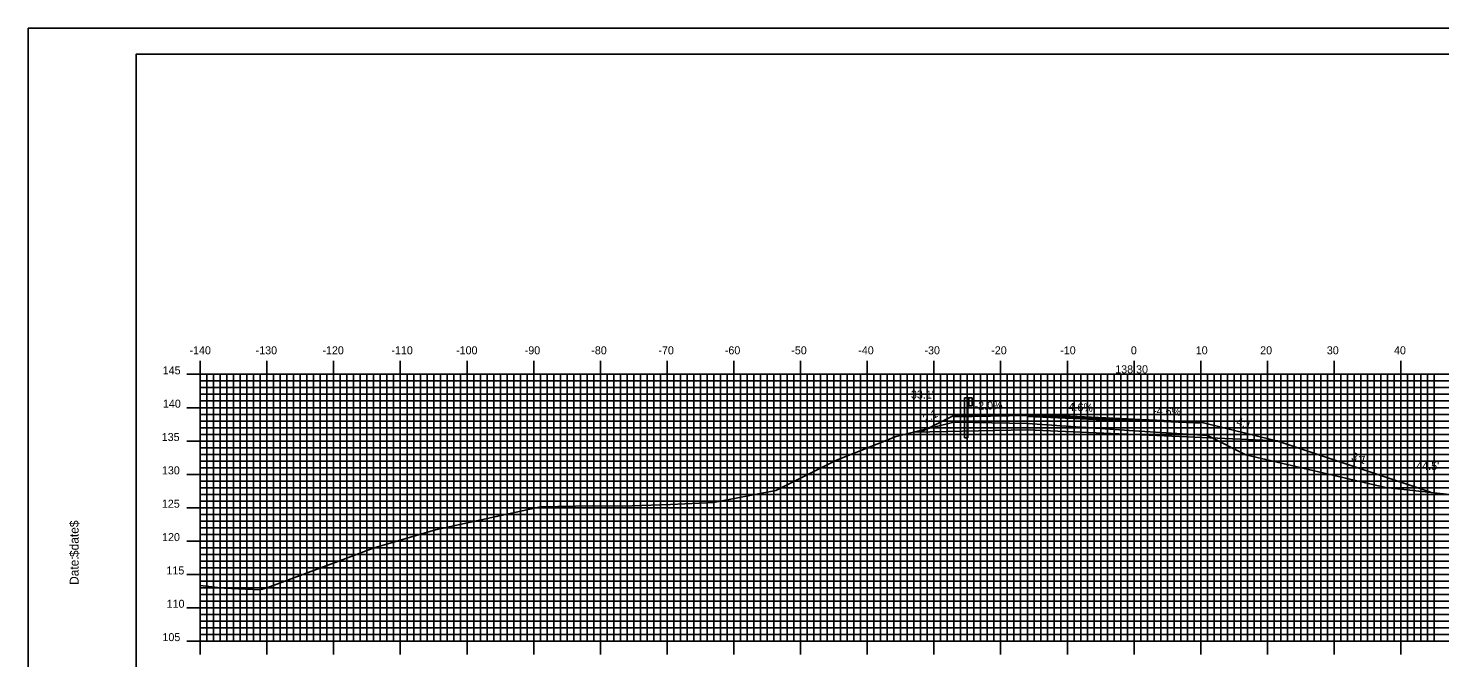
# Model space of a CAD drawing. Extents: x 851753 to 852097, y 364661 to 364881.
# Drawn here: x 851753.5 to 851965.1, y 364786.9 to 364881.3 of the extents above; entities that cross this region are included whole.
import ezdxf

# ---------------------------------------------------------------- set-up
doc = ezdxf.new("R2010")
doc.units = 0
for name, color, linetype in [('ANNOTATION', 7, 'Continuous'), ('BORDER', 7, 'Continuous'), ('D_Guardrail_Beam_Lt', 7, 'Continuous'), ('D_Roadway_Centerline_Text', 7, 'Continuous'), ('D_Roadway_Edge_Shoulder', 7, 'Continuous'), ('D_Roadway_Edge_TW', 7, 'Continuous'), ('D_Roadway_Pavement', 7, 'Continuous'), ('D_Roadway_SlopeLines', 7, 'Continuous'), ('D_Roadway_SubGrade', 7, 'Continuous'), ('D_Text_Standard', 7, 'Continuous'), ('H_V ANNOTATION', 7, 'Continuous'), ('M_Roadway_Centerline', 7, 'Continuous'), ('MAJOR', 7, 'Continuous'), ('MINOR', 7, 'Continuous'), ('PLOT BOUNDARY', 7, 'Continuous'), ('S_Roadway_Centerline', 7, 'Continuous')]:
    doc.layers.add(name, color=color, linetype=linetype)

msp = doc.modelspace()

# ---------------------------------------------------------------- linework, layer by layer
at = {"layer": 'BORDER'}
msp.add_lwpolyline([(851769.64, 364667.37), (852089.64, 364667.37), (852089.64, 364877.37), (851769.64, 364877.37)], close=True, dxfattribs=at)
at = {"layer": 'D_Guardrail_Beam_Lt'}
for p, q in [((851893.81, 364825.83), (851893.81, 364819.83)), ((851894.28, 364825.83), (851893.81, 364825.83)), ((851894.97, 364825.83), (851894.28, 364825.83)), ((851894.28, 364825.83), (851894.28, 364824.66)), ((851894.28, 364824.66), (851894.97, 364824.66)), ((851894.3, 364819.83), (851894.3, 364824.66)), ((851894.35, 364825.83), (851894.35, 364824.66)), ((851894.45, 364825.83), (851894.45, 364824.66)), ((851894.97, 364824.66), (851894.97, 364825.83)), ((851894.97, 364825.74), (851895.05, 364825.73)), ((851895.05, 364824.76), (851894.97, 364824.74)), ((851894.98, 364825.28), (851894.98, 364825.21)), ((851895.2, 364825.48), (851895.01, 364825.34)), ((851895.01, 364825.14), (851895.2, 364825.01)), ((851895.06, 364825.72), (851895.2, 364825.62)), ((851895.2, 364824.86), (851895.06, 364824.76)), ((851894.3, 364819.83), (851893.81, 364819.83))]:
    msp.add_line(p, q, dxfattribs=at)
for centre, major_axis, start_param, end_param in [((851895.05, 364825.28), (-0.0789, 0), 5.323254, 6.283185), ((851895.05, 364825.21), (-0.0789, 0), 6.283185, 7.243116), ((851895.04, 364825.69), (0.0417, 0), 0.959931, 1.376053), ((851895.04, 364824.8), (0.0417, 0), 4.907132, 5.323254), ((851895.15, 364825.55), (0.0877, 0), 5.323254, 7.243116), ((851895.15, 364824.94), (0.0877, 0), 5.323254, 7.243116)]:
    msp.add_ellipse(centre, major_axis=major_axis, ratio=0.995501, start_param=start_param, end_param=end_param, dxfattribs=at)
at = {"layer": 'D_Roadway_Edge_Shoulder'}
msp.add_lwpolyline([(851903.24, 364823.4), (851892.24, 364823.18), (851892.24, 364823.02), (851903.24, 364823.21)], close=True, dxfattribs=at)
at = {"layer": 'D_Roadway_Edge_TW'}
msp.add_line((851919.24, 364822.67), (851929.24, 364822.21), dxfattribs=at)
msp.add_lwpolyline([(851903.24, 364823.4), (851919.24, 364822.67), (851919.24, 364822.5), (851903.24, 364823.21)], close=True, dxfattribs=at)
msp.add_lwpolyline([(851919.24, 364822.5), (851929.24, 364822.04), (851929.24, 364822.21)], dxfattribs=at)
at = {"layer": 'D_Roadway_Pavement'}
msp.add_lwpolyline([(851903.24, 364823.21), (851919.24, 364822.5), (851919.24, 364822.33), (851903.24, 364823.05)], close=True, dxfattribs=at)
for points in [[(851903.24, 364823.21), (851903.24, 364823.05)], [(851919.24, 364822.5), (851919.24, 364822.33)], [(851919.24, 364822.5), (851919.24, 364822.33)]]:
    msp.add_lwpolyline(points, dxfattribs=at)
at = {"layer": 'D_Roadway_SlopeLines'}
msp.add_line((851892.24, 364823.18), (851887.33, 364820.73), dxfattribs=at)
msp.add_lwpolyline([(851929.24, 364822.21), (851940.77, 364819.33), (851963.41, 364811.78)], dxfattribs=at)
at = {"layer": 'D_Roadway_SubGrade'}
for p, q in [((851919.24, 364820.33), (851940.77, 364819.39)), ((851963.41, 364811.78), (851963.77, 364811.66))]:
    msp.add_line(p, q, dxfattribs=at)
msp.add_lwpolyline([(851903.24, 364823.05), (851919.24, 364822.33), (851919.24, 364820.33), (851903.24, 364821.05)], close=True, dxfattribs=at)
msp.add_lwpolyline([(851903.24, 364821.98), (851903.24, 364821.05), (851886.18, 364820.7)], dxfattribs=at)
at = {"layer": 'MAJOR'}
for p, q in [((851779.24, 364831.37), (851779.24, 364829.37)), ((851789.24, 364831.37), (851789.24, 364829.37)), ((851799.24, 364831.37), (851799.24, 364829.37)), ((851809.24, 364831.37), (851809.24, 364829.37)), ((851819.24, 364831.37), (851819.24, 364829.37)), ((851829.24, 364831.37), (851829.24, 364829.37)), ((851839.24, 364831.37), (851839.24, 364829.37)), ((851849.24, 364831.37), (851849.24, 364829.37)), ((851859.24, 364831.37), (851859.24, 364829.37)), ((851869.24, 364831.37), (851869.24, 364829.37)), ((851879.24, 364831.37), (851879.24, 364829.37)), ((851889.24, 364831.37), (851889.24, 364829.37)), ((851899.24, 364831.37), (851899.24, 364829.37)), ((851909.24, 364831.37), (851909.24, 364829.37)), ((851919.24, 364831.37), (851919.24, 364829.37)), ((851929.24, 364831.37), (851929.24, 364829.37)), ((851939.24, 364831.37), (851939.24, 364829.37)), ((851949.24, 364831.37), (851949.24, 364829.37)), ((851959.24, 364831.37), (851959.24, 364829.37)), ((851777.24, 364829.37), (851779.24, 364829.37)), ((851779.24, 364829.37), (852059.24, 364829.37)), ((851779.24, 364789.37), (851779.24, 364829.37)), ((851779.24, 364789.37), (851779.24, 364829.37)), ((851779.24, 364829.37), (852059.24, 364829.37)), ((851789.24, 364789.37), (851789.24, 364829.37)), ((851799.24, 364789.37), (851799.24, 364829.37)), ((851809.24, 364789.37), (851809.24, 364829.37)), ((851819.24, 364789.37), (851819.24, 364829.37)), ((851829.24, 364789.37), (851829.24, 364829.37)), ((851839.24, 364789.37), (851839.24, 364829.37)), ((851849.24, 364789.37), (851849.24, 364829.37)), ((851859.24, 364789.37), (851859.24, 364829.37)), ((851869.24, 364789.37), (851869.24, 364829.37)), ((851879.24, 364789.37), (851879.24, 364829.37)), ((851889.24, 364789.37), (851889.24, 364829.37)), ((851899.24, 364789.37), (851899.24, 364829.37)), ((851909.24, 364789.37), (851909.24, 364829.37)), ((851919.24, 364789.37), (851919.24, 364829.37)), ((851929.24, 364789.37), (851929.24, 364829.37)), ((851939.24, 364789.37), (851939.24, 364829.37)), ((851949.24, 364789.37), (851949.24, 364829.37)), ((851959.24, 364789.37), (851959.24, 364829.37)), ((851777.24, 364824.37), (851779.24, 364824.37)), ((851779.24, 364824.37), (852059.24, 364824.37)), ((851777.24, 364819.37), (851779.24, 364819.37)), ((851779.24, 364819.37), (852059.24, 364819.37)), ((851777.24, 364814.37), (851779.24, 364814.37)), ((851779.24, 364814.37), (852059.24, 364814.37)), ((851777.24, 364809.37), (851779.24, 364809.37)), ((851779.24, 364809.37), (852059.24, 364809.37)), ((851777.24, 364804.37), (851779.24, 364804.37)), ((851779.24, 364804.37), (852059.24, 364804.37)), ((851777.24, 364799.37), (851779.24, 364799.37)), ((851779.24, 364799.37), (852059.24, 364799.37)), ((851777.24, 364794.37), (851779.24, 364794.37)), ((851779.24, 364794.37), (852059.24, 364794.37)), ((851777.24, 364789.37), (851779.24, 364789.37)), ((851779.24, 364789.37), (852059.24, 364789.37)), ((851779.24, 364789.37), (852059.24, 364789.37)), ((851779.24, 364787.37), (851779.24, 364789.37)), ((851789.24, 364787.37), (851789.24, 364789.37)), ((851799.24, 364787.37), (851799.24, 364789.37)), ((851809.24, 364787.37), (851809.24, 364789.37)), ((851819.24, 364787.37), (851819.24, 364789.37)), ((851829.24, 364787.37), (851829.24, 364789.37)), ((851839.24, 364787.37), (851839.24, 364789.37)), ((851849.24, 364787.37), (851849.24, 364789.37)), ((851859.24, 364787.37), (851859.24, 364789.37)), ((851869.24, 364787.37), (851869.24, 364789.37)), ((851879.24, 364787.37), (851879.24, 364789.37)), ((851889.24, 364787.37), (851889.24, 364789.37)), ((851899.24, 364787.37), (851899.24, 364789.37)), ((851909.24, 364787.37), (851909.24, 364789.37)), ((851919.24, 364787.37), (851919.24, 364789.37)), ((851929.24, 364787.37), (851929.24, 364789.37)), ((851939.24, 364787.37), (851939.24, 364789.37)), ((851949.24, 364787.37), (851949.24, 364789.37)), ((851959.24, 364787.37), (851959.24, 364789.37))]:
    msp.add_line(p, q, dxfattribs=at)
at = {"layer": 'MINOR'}
for p, q in [((851780.24, 364789.37), (851780.24, 364829.37)), ((851781.24, 364789.37), (851781.24, 364829.37)), ((851782.24, 364789.37), (851782.24, 364829.37)), ((851783.24, 364789.37), (851783.24, 364829.37)), ((851784.24, 364789.37), (851784.24, 364829.37)), ((851785.24, 364789.37), (851785.24, 364829.37)), ((851786.24, 364789.37), (851786.24, 364829.37)), ((851787.24, 364789.37), (851787.24, 364829.37)), ((851788.24, 364789.37), (851788.24, 364829.37)), ((851790.24, 364789.37), (851790.24, 364829.37)), ((851791.24, 364789.37), (851791.24, 364829.37)), ((851792.24, 364789.37), (851792.24, 364829.37)), ((851793.24, 364789.37), (851793.24, 364829.37)), ((851794.24, 364789.37), (851794.24, 364829.37)), ((851795.24, 364789.37), (851795.24, 364829.37)), ((851796.24, 364789.37), (851796.24, 364829.37)), ((851797.24, 364789.37), (851797.24, 364829.37)), ((851798.24, 364789.37), (851798.24, 364829.37)), ((851800.24, 364789.37), (851800.24, 364829.37)), ((851801.24, 364789.37), (851801.24, 364829.37)), ((851802.24, 364789.37), (851802.24, 364829.37)), ((851803.24, 364789.37), (851803.24, 364829.37)), ((851804.24, 364789.37), (851804.24, 364829.37)), ((851805.24, 364789.37), (851805.24, 364829.37)), ((851806.24, 364789.37), (851806.24, 364829.37)), ((851807.24, 364789.37), (851807.24, 364829.37)), ((851808.24, 364789.37), (851808.24, 364829.37)), ((851810.24, 364789.37), (851810.24, 364829.37)), ((851811.24, 364789.37), (851811.24, 364829.37)), ((851812.24, 364789.37), (851812.24, 364829.37)), ((851813.24, 364789.37), (851813.24, 364829.37)), ((851814.24, 364789.37), (851814.24, 364829.37)), ((851815.24, 364789.37), (851815.24, 364829.37)), ((851816.24, 364789.37), (851816.24, 364829.37)), ((851817.24, 364789.37), (851817.24, 364829.37)), ((851818.24, 364789.37), (851818.24, 364829.37)), ((851820.24, 364789.37), (851820.24, 364829.37)), ((851821.24, 364789.37), (851821.24, 364829.37)), ((851822.24, 364789.37), (851822.24, 364829.37)), ((851823.24, 364789.37), (851823.24, 364829.37)), ((851824.24, 364789.37), (851824.24, 364829.37)), ((851825.24, 364789.37), (851825.24, 364829.37)), ((851826.24, 364789.37), (851826.24, 364829.37)), ((851827.24, 364789.37), (851827.24, 364829.37)), ((851828.24, 364789.37), (851828.24, 364829.37)), ((851830.24, 364789.37), (851830.24, 364829.37)), ((851831.24, 364789.37), (851831.24, 364829.37)), ((851832.24, 364789.37), (851832.24, 364829.37)), ((851833.24, 364789.37), (851833.24, 364829.37)), ((851834.24, 364789.37), (851834.24, 364829.37)), ((851835.24, 364789.37), (851835.24, 364829.37)), ((851836.24, 364789.37), (851836.24, 364829.37)), ((851837.24, 364789.37), (851837.24, 364829.37)), ((851838.24, 364789.37), (851838.24, 364829.37)), ((851840.24, 364789.37), (851840.24, 364829.37)), ((851841.24, 364789.37), (851841.24, 364829.37)), ((851842.24, 364789.37), (851842.24, 364829.37)), ((851843.24, 364789.37), (851843.24, 364829.37)), ((851844.24, 364789.37), (851844.24, 364829.37)), ((851845.24, 364789.37), (851845.24, 364829.37)), ((851846.24, 364789.37), (851846.24, 364829.37)), ((851847.24, 364789.37), (851847.24, 364829.37)), ((851848.24, 364789.37), (851848.24, 364829.37)), ((851850.24, 364789.37), (851850.24, 364829.37)), ((851851.24, 364789.37), (851851.24, 364829.37)), ((851852.24, 364789.37), (851852.24, 364829.37)), ((851853.24, 364789.37), (851853.24, 364829.37)), ((851854.24, 364789.37), (851854.24, 364829.37)), ((851855.24, 364789.37), (851855.24, 364829.37)), ((851856.24, 364789.37), (851856.24, 364829.37)), ((851857.24, 364789.37), (851857.24, 364829.37)), ((851858.24, 364789.37), (851858.24, 364829.37)), ((851860.24, 364789.37), (851860.24, 364829.37)), ((851861.24, 364789.37), (851861.24, 364829.37)), ((851862.24, 364789.37), (851862.24, 364829.37)), ((851863.24, 364789.37), (851863.24, 364829.37)), ((851864.24, 364789.37), (851864.24, 364829.37)), ((851865.24, 364789.37), (851865.24, 364829.37)), ((851866.24, 364789.37), (851866.24, 364829.37)), ((851867.24, 364789.37), (851867.24, 364829.37)), ((851868.24, 364789.37), (851868.24, 364829.37)), ((851870.24, 364789.37), (851870.24, 364829.37)), ((851871.24, 364789.37), (851871.24, 364829.37)), ((851872.24, 364789.37), (851872.24, 364829.37)), ((851873.24, 364789.37), (851873.24, 364829.37)), ((851874.24, 364789.37), (851874.24, 364829.37)), ((851875.24, 364789.37), (851875.24, 364829.37)), ((851876.24, 364789.37), (851876.24, 364829.37)), ((851877.24, 364789.37), (851877.24, 364829.37)), ((851878.24, 364789.37), (851878.24, 364829.37)), ((851880.24, 364789.37), (851880.24, 364829.37)), ((851881.24, 364789.37), (851881.24, 364829.37)), ((851882.24, 364789.37), (851882.24, 364829.37)), ((851883.24, 364789.37), (851883.24, 364829.37)), ((851884.24, 364789.37), (851884.24, 364829.37)), ((851885.24, 364789.37), (851885.24, 364829.37)), ((851886.24, 364789.37), (851886.24, 364829.37)), ((851887.24, 364789.37), (851887.24, 364829.37)), ((851888.24, 364789.37), (851888.24, 364829.37)), ((851890.24, 364789.37), (851890.24, 364829.37)), ((851891.24, 364789.37), (851891.24, 364829.37)), ((851892.24, 364789.37), (851892.24, 364829.37)), ((851893.24, 364789.37), (851893.24, 364829.37)), ((851894.24, 364789.37), (851894.24, 364829.37)), ((851895.24, 364789.37), (851895.24, 364829.37)), ((851896.24, 364789.37), (851896.24, 364829.37)), ((851897.24, 364789.37), (851897.24, 364829.37)), ((851898.24, 364789.37), (851898.24, 364829.37)), ((851900.24, 364789.37), (851900.24, 364829.37)), ((851901.24, 364789.37), (851901.24, 364829.37)), ((851902.24, 364789.37), (851902.24, 364829.37)), ((851903.24, 364789.37), (851903.24, 364829.37)), ((851904.24, 364789.37), (851904.24, 364829.37)), ((851905.24, 364789.37), (851905.24, 364829.37)), ((851906.24, 364789.37), (851906.24, 364829.37)), ((851907.24, 364789.37), (851907.24, 364829.37)), ((851908.24, 364789.37), (851908.24, 364829.37)), ((851910.24, 364789.37), (851910.24, 364829.37)), ((851911.24, 364789.37), (851911.24, 364829.37)), ((851912.24, 364789.37), (851912.24, 364829.37)), ((851913.24, 364789.37), (851913.24, 364829.37)), ((851914.24, 364789.37), (851914.24, 364829.37)), ((851915.24, 364789.37), (851915.24, 364829.37)), ((851916.24, 364789.37), (851916.24, 364829.37)), ((851917.24, 364789.37), (851917.24, 364829.37)), ((851918.24, 364789.37), (851918.24, 364829.37)), ((851920.24, 364789.37), (851920.24, 364829.37)), ((851921.24, 364789.37), (851921.24, 364829.37)), ((851922.24, 364789.37), (851922.24, 364829.37)), ((851923.24, 364789.37), (851923.24, 364829.37)), ((851924.24, 364789.37), (851924.24, 364829.37)), ((851925.24, 364789.37), (851925.24, 364829.37)), ((851926.24, 364789.37), (851926.24, 364829.37)), ((851927.24, 364789.37), (851927.24, 364829.37)), ((851928.24, 364789.37), (851928.24, 364829.37)), ((851930.24, 364789.37), (851930.24, 364829.37)), ((851931.24, 364789.37), (851931.24, 364829.37)), ((851932.24, 364789.37), (851932.24, 364829.37)), ((851933.24, 364789.37), (851933.24, 364829.37)), ((851934.24, 364789.37), (851934.24, 364829.37)), ((851935.24, 364789.37), (851935.24, 364829.37)), ((851936.24, 364789.37), (851936.24, 364829.37)), ((851937.24, 364789.37), (851937.24, 364829.37)), ((851938.24, 364789.37), (851938.24, 364829.37)), ((851940.24, 364789.37), (851940.24, 364829.37)), ((851941.24, 364789.37), (851941.24, 364829.37)), ((851942.24, 364789.37), (851942.24, 364829.37)), ((851943.24, 364789.37), (851943.24, 364829.37)), ((851944.24, 364789.37), (851944.24, 364829.37)), ((851945.24, 364789.37), (851945.24, 364829.37)), ((851946.24, 364789.37), (851946.24, 364829.37)), ((851947.24, 364789.37), (851947.24, 364829.37)), ((851948.24, 364789.37), (851948.24, 364829.37)), ((851950.24, 364789.37), (851950.24, 364829.37)), ((851951.24, 364789.37), (851951.24, 364829.37)), ((851952.24, 364789.37), (851952.24, 364829.37)), ((851953.24, 364789.37), (851953.24, 364829.37)), ((851954.24, 364789.37), (851954.24, 364829.37)), ((851955.24, 364789.37), (851955.24, 364829.37)), ((851956.24, 364789.37), (851956.24, 364829.37)), ((851957.24, 364789.37), (851957.24, 364829.37)), ((851958.24, 364789.37), (851958.24, 364829.37)), ((851960.24, 364789.37), (851960.24, 364829.37)), ((851961.24, 364789.37), (851961.24, 364829.37)), ((851962.24, 364789.37), (851962.24, 364829.37)), ((851963.24, 364789.37), (851963.24, 364829.37)), ((851964.24, 364789.37), (851964.24, 364829.37)), ((851779.24, 364828.37), (852059.24, 364828.37)), ((851779.24, 364828.37), (851781.25, 364828.37)), ((851779.24, 364827.37), (852059.24, 364827.37)), ((851779.24, 364827.37), (851781.25, 364827.37)), ((851779.24, 364826.37), (852059.24, 364826.37)), ((851779.24, 364826.37), (851781.25, 364826.37)), ((851779.24, 364825.37), (852059.24, 364825.37)), ((851779.24, 364825.37), (851781.25, 364825.37)), ((851779.24, 364823.37), (852059.24, 364823.37)), ((851779.24, 364823.37), (851781.25, 364823.37)), ((851779.24, 364822.37), (852059.24, 364822.37)), ((851779.24, 364822.37), (851781.25, 364822.37)), ((851779.24, 364821.37), (852059.24, 364821.37)), ((851779.24, 364821.37), (851781.25, 364821.37)), ((851779.24, 364820.37), (852059.24, 364820.37)), ((851779.24, 364820.37), (851781.25, 364820.37)), ((851779.24, 364818.37), (852059.24, 364818.37)), ((851779.24, 364818.37), (851781.25, 364818.37)), ((851779.24, 364817.37), (852059.24, 364817.37)), ((851779.24, 364817.37), (851781.25, 364817.37)), ((851779.24, 364816.37), (852059.24, 364816.37)), ((851779.24, 364816.37), (851781.25, 364816.37)), ((851779.24, 364815.37), (852059.24, 364815.37)), ((851779.24, 364815.37), (851781.25, 364815.37)), ((851779.24, 364813.37), (852059.24, 364813.37)), ((851779.24, 364813.37), (851781.25, 364813.37)), ((851779.24, 364812.37), (852059.24, 364812.37)), ((851779.24, 364812.37), (851781.25, 364812.37)), ((851779.24, 364811.37), (852059.24, 364811.37)), ((851779.24, 364811.37), (851781.25, 364811.37)), ((851779.24, 364810.37), (852059.24, 364810.37)), ((851779.24, 364810.37), (851781.25, 364810.37)), ((851779.24, 364808.37), (852059.24, 364808.37)), ((851779.24, 364808.37), (851781.25, 364808.37)), ((851779.24, 364807.37), (852059.24, 364807.37)), ((851779.24, 364807.37), (851781.25, 364807.37)), ((851779.24, 364806.37), (852059.24, 364806.37)), ((851779.24, 364806.37), (851781.25, 364806.37)), ((851779.24, 364805.37), (852059.24, 364805.37)), ((851779.24, 364805.37), (851781.25, 364805.37)), ((851779.24, 364803.37), (852059.24, 364803.37)), ((851779.24, 364803.37), (851781.25, 364803.37)), ((851779.24, 364802.37), (852059.24, 364802.37)), ((851779.24, 364802.37), (851781.25, 364802.37)), ((851779.24, 364801.37), (852059.24, 364801.37)), ((851779.24, 364801.37), (851781.25, 364801.37)), ((851779.24, 364800.37), (852059.24, 364800.37)), ((851779.24, 364800.37), (851781.25, 364800.37)), ((851779.24, 364798.37), (852059.24, 364798.37)), ((851779.24, 364798.37), (851781.25, 364798.37)), ((851779.24, 364797.37), (852059.24, 364797.37)), ((851779.24, 364797.37), (851781.25, 364797.37)), ((851779.24, 364796.37), (852059.24, 364796.37)), ((851779.24, 364796.37), (851781.25, 364796.37)), ((851779.24, 364795.37), (852059.24, 364795.37)), ((851779.24, 364795.37), (851781.25, 364795.37)), ((851779.24, 364793.37), (852059.24, 364793.37)), ((851779.24, 364793.37), (851781.25, 364793.37)), ((851779.24, 364792.37), (852059.24, 364792.37)), ((851779.24, 364792.37), (851781.25, 364792.37)), ((851779.24, 364791.37), (852059.24, 364791.37)), ((851779.24, 364791.37), (851781.25, 364791.37)), ((851779.24, 364790.37), (852059.24, 364790.37)), ((851779.24, 364790.37), (851781.25, 364790.37))]:
    msp.add_line(p, q, dxfattribs=at)
at = {"layer": 'PLOT BOUNDARY'}
msp.add_lwpolyline([(851753.46, 364661.25), (852093.46, 364661.25), (852093.46, 364881.25), (851753.46, 364881.25)], close=True, dxfattribs=at)
at = {"layer": 'S_Roadway_Centerline'}
for points in [[(851883.05, 364819.92), (851883.6, 364820.06), (851892.24, 364822.22), (851895.24, 364822.15), (851903.24, 364821.98), (851919.24, 364820.92), (851927.24, 364820.39), (851930.24, 364820.2), (851936, 364817.32), (851956.94, 364812.41)], [(851779.24, 364797.73), (851782.28, 364797.37), (851782.88, 364797.3), (851788.18, 364797.04), (851789.38, 364797.43), (851800.29, 364801.47), (851805.3, 364803.38), (851814.49, 364806.05), (851830.23, 364809.5), (851838.12, 364809.64), (851842.55, 364809.62), (851849.74, 364809.84), (851856.17, 364810.15), (851865.56, 364811.95), (851874.64, 364816.51), (851883.6, 364820.06)], [(851956.94, 364812.41), (851970.64, 364810.91), (851976.37, 364810.17), (851985.62, 364809.64), (851988.76, 364809.53), (851991.75, 364809.86), (851995.97, 364809.93), (852006.23, 364810.09), (852020.7, 364810.38), (852024.02, 364810.48), (852035.16, 364810.81), (852037.84, 364810.86), (852039.57, 364810.75), (852043.09, 364810.94), (852053.55, 364811.48), (852059.24, 364811.87)]]:
    msp.add_lwpolyline(points, dxfattribs=at)

# ---------------------------------------------------------------- texts
at = {"layer": 'ANNOTATION'}
for s, rotation, p in [('-2.0%', 1.1458, (851895.35, 364824.05)), ('4.6%', 357.3663, (851909.39, 364823.92)), ('-4.6%', 357.3663, (851922.07, 364823.34)), ('2:1', 26.5651, (851887.93, 364822.06)), ('4:1', 345.9638, (851934.51, 364821.75)), ('3:1', 341.5652, (851951.69, 364816.59))]:
    msp.add_text(s, height=1.2, rotation=rotation, dxfattribs=at).set_placement(p)
at = {"layer": 'BORDER'}
for s, p in [('$date$', (851761.01, 364801.98)), ('Date:', (851761.01, 364797.8))]:
    msp.add_text(s, height=1.339, rotation=90, dxfattribs=at).set_placement(p)
at = {"layer": 'D_Roadway_Centerline_Text'}
msp.add_text('138.30', height=1.2, dxfattribs=at).set_placement((851916.42, 364829.52))
at = {"layer": 'D_Text_Standard'}
for s, p in [("33.1'", (851885.79, 364825.74)), ("44.5'", (851961.55, 364815.04))]:
    msp.add_text(s, height=1.2, dxfattribs=at).set_placement(p)
at = {"layer": 'H_V ANNOTATION'}
for s, p in [('-140', (851777.63, 364832.37)), ('-130', (851787.55, 364832.37)), ('-120', (851797.56, 364832.37)), ('-110', (851807.9, 364832.37)), ('-100', (851817.6, 364832.37)), ('-90', (851827.89, 364832.37)), ('-80', (851837.87, 364832.37)), ('-70', (851847.93, 364832.37)), ('-60', (851857.89, 364832.37)), ('-50', (851867.85, 364832.37)), ('-40', (851877.89, 364832.37)), ('-30', (851887.82, 364832.37)), ('-20', (851897.83, 364832.37)), ('-10', (851908.17, 364832.37)), ('0', (851918.76, 364832.37)), ('10', (851928.49, 364832.37)), ('20', (851938.15, 364832.37)), ('30', (851948.14, 364832.37)), ('40', (851958.21, 364832.37)), ('145', (851773.62, 364829.37)), ('140', (851773.65, 364824.37)), ('135', (851773.47, 364819.37)), ('130', (851773.5, 364814.37)), ('125', (851773.49, 364809.37)), ('120', (851773.52, 364804.37)), ('115', (851774.18, 364799.37)), ('110', (851774.21, 364794.37)), ('105', (851773.58, 364789.37))]:
    msp.add_text(s, height=1.2, dxfattribs=at).set_placement(p)
at = {"layer": 'M_Roadway_Centerline'}
for s, p in [('C', (851906.11, 364821.78)), ('L', (851906.12, 364821.78))]:
    msp.add_text(s, height=0.0146, dxfattribs=at).set_placement(p)
at = {"layer": 'MAJOR'}
msp.add_text('-', height=0.012, dxfattribs=at).set_placement((851779.23, 364789.37))

doc.saveas('drawing.dxf')
